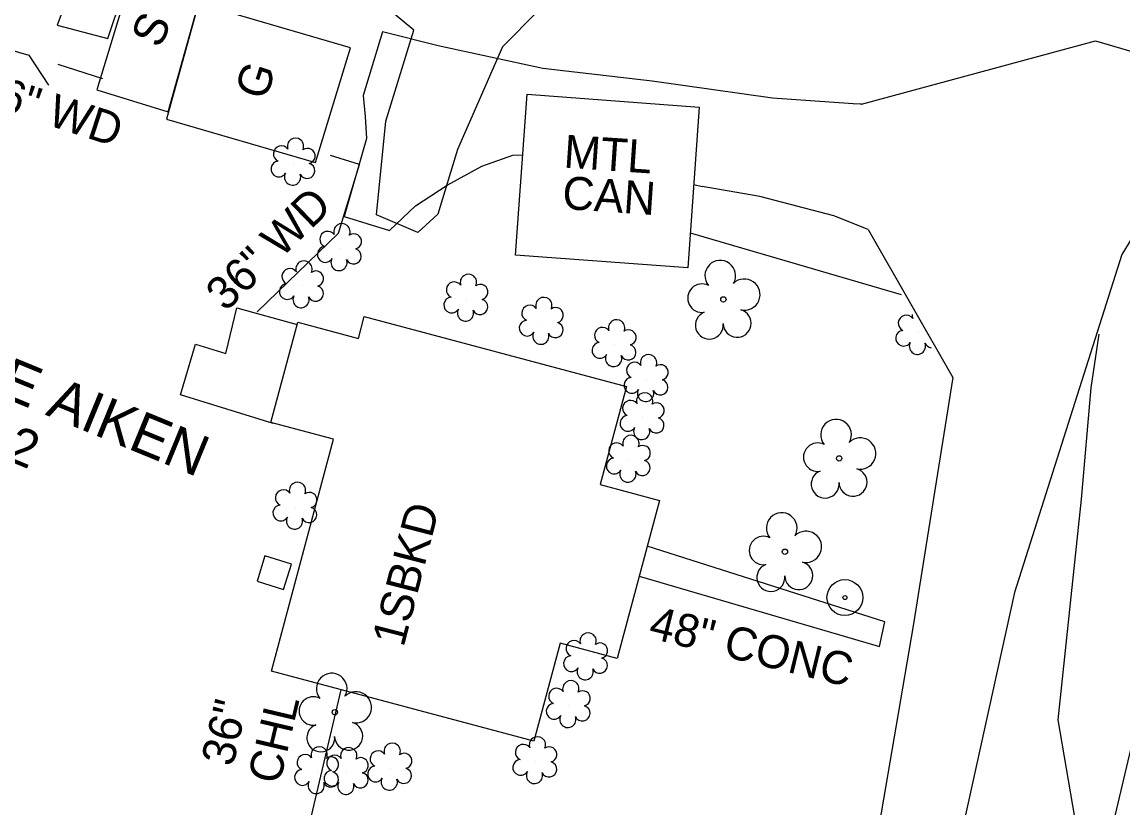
# Model space of a CAD drawing. Extents: x 2089016 to 2094354, y 862840 to 864725.
# Drawn here: x 2091346.4 to 2091480, y 864122.7 to 864218.1 of the extents above; entities that cross this region are included whole.
import ezdxf

# ---------------------------------------------------------------- set-up
doc = ezdxf.new("R2010")
doc.units = 0
for name, color, linetype in [('Exist Building', 7, 'Continuous'), ('Exist Building Metal Canopy', 7, 'Continuous'), ('Exist Building Metal Canopy Text', 7, 'Continuous'), ('Exist Building Text', 7, 'Continuous'), ('Exist Other Culture Area Outline', 7, 'Continuous'), ('Exist Other Culture Area Outline Text', 7, 'Continuous'), ('Exist Other Culture Fence Line', 7, 'Continuous'), ('Exist Other Culture Fence Line Text', 7, 'Continuous'), ('Exist Other Culture Gate', 7, 'Continuous'), ('Exist Property Deed Book Text', 7, 'Continuous'), ('Exist Property Owner Text', 7, 'Continuous'), ('Exist Right of Way Line', 7, 'Continuous'), ('Exist Roads EOP', 7, 'Continuous'), ('Exist Roads Soil', 7, 'Continuous'), ('Exist Vegetation Shrub CELL', 7, 'Continuous'), ('Exist Vegetation Tree CELL', 7, 'Continuous'), ('Exist Vegetation Woods Line', 7, 'Continuous'), ('Prop Drainage Structure Pipe RCP 36in Class IV', 7, 'Continuous')]:
    doc.layers.add(name, color=color, linetype=linetype)

msp = doc.modelspace()

# ---------------------------------------------------------------- linework, layer by layer
at = {"layer": 'Exist Building'}
for points in [[(2091361.02, 864228.09), (2091355.49, 864209.85), (2091364.16, 864207.19), (2091369.4, 864226)], [(2091352.8, 864223.34), (2091350.7, 864217.69), (2091356.82, 864216.07), (2091358.59, 864221.42)], [(2091367.85, 864220.35), (2091363.93, 864206.31), (2091382.04, 864201.05), (2091386.29, 864214.97)], [(2091376.68, 864139.32), (2091384.22, 864167.45), (2091376.6, 864169.49), (2091379.87, 864181.67), (2091387.24, 864179.69), (2091387.95, 864182.36), (2091419.75, 864173.86), (2091416.57, 864161.97), (2091423.77, 864160.04), (2091418.64, 864140.85), (2091411.7, 864142.7), (2091408.52, 864130.81)]]:
    msp.add_lwpolyline(points, close=True, dxfattribs=at)
at = {"layer": 'Exist Building Metal Canopy'}
msp.add_lwpolyline([(2091427.19, 864188.24), (2091406.31, 864189.81), (2091407.71, 864209.34), (2091428.59, 864207.77)], close=True, dxfattribs=at)
at = {"layer": 'Exist Other Culture Area Outline'}
for points in [[(2091376.9, 864169.39), (2091365.66, 864172.84), (2091367.47, 864178.98), (2091371.13, 864177.85), (2091372.47, 864183.4), (2091379.79, 864181.37)], [(2091421.31, 864150.84), (2091450.46, 864142.33), (2091451.11, 864145.32), (2091422.28, 864154.47)]]:
    msp.add_lwpolyline(points, dxfattribs=at)
msp.add_lwpolyline([(2091375.88, 864153.31), (2091374.93, 864150.22), (2091378.16, 864149.23), (2091379.11, 864152.31)], close=True, dxfattribs=at)
at = {"layer": 'Exist Other Culture Fence Line'}
for p, q in [((2091350.75, 864212.96), (2091356.17, 864211.24)), ((2091384.8, 864192.45), (2091374.95, 864182.92)), ((2091427.5, 864192.52), (2091453.07, 864185.04)), ((2091374.68, 864092.67), (2091385.15, 864137.06))]:
    msp.add_line(p, q, dxfattribs=at)
for points in [[(2091361.35, 864227.74), (2091341.2, 864232.73), (2091337.45, 864216.91), (2091347.25, 864214.07)], [(2091384.8, 864192.45), (2091387.35, 864200.79), (2091383.84, 864201.88)]]:
    msp.add_lwpolyline(points, dxfattribs=at)
at = {"layer": 'Exist Other Culture Gate'}
msp.add_line((2091347.25, 864214.07), (2091349.63, 864210.42), dxfattribs=at)
at = {"layer": 'Exist Right of Way Line'}
msp.add_line((2091452.8, 864010.25), (2091484.62, 864145.5), dxfattribs=at)
at = {"layer": 'Exist Roads EOP'}
for points in [[(2091441.1, 863921.91), (2091444.26, 863930.54), (2091451.5, 863951.02), (2091462.11, 863990.03), (2091470.34, 864025.4), (2091478.72, 864061.83), (2091488.18, 864099.79), (2091497.28, 864140.14), (2091508.39, 864182.61), (2091520.43, 864222.63), (2091532.13, 864263.12), (2091539.24, 864279.17)], [(2091458.4, 863915.67), (2091461.42, 863924.49), (2091469.42, 863944.94), (2091479.75, 863985.59), (2091486.04, 864011.02), (2091487.65, 864016.26), (2091489.53, 864018.43), (2091490.64, 864021.54), (2091491.12, 864028.71), (2091491.12, 864035.24), (2091495.79, 864056.26), (2091504.17, 864091.54), (2091506.21, 864096.08), (2091508.03, 864097.81), (2091509.43, 864104.3), (2091510.9, 864108.46), (2091509.69, 864112.64), (2091510.21, 864116.03), (2091515.22, 864135.56), (2091526.19, 864178.07), (2091537.83, 864216.97), (2091551.26, 864256.55)], [(2090159.86, 864177.45), (2090180.67, 864168.73), (2090222.86, 864151.65), (2090264.39, 864134.6), (2090306, 864117.79), (2090347.24, 864101.05), (2090392.99, 864082.57), (2090433.2, 864065.09), (2090472.83, 864048.96), (2090514.73, 864032.43), (2090559.97, 864014.05), (2090601.37, 863997.19), (2090646.29, 863978.82), (2090688.95, 863961.27), (2090733.38, 863942.96), (2090770.05, 863927.33), (2090814.52, 863908.72), (2090858.91, 863891), (2090901.15, 863874.17), (2090939.87, 863858.28), (2090962.72, 863848.64), (2090997.54, 863834.72), (2091036.07, 863819.08), (2091075.6, 863802.48), (2091112.88, 863787.77), (2091153.64, 863770.65), (2091194.67, 863753.49), (2091234.07, 863737.23), (2091276.57, 863719.33), (2091296.56, 863710.75), (2091332.88, 863695.67), (2091370.71, 863680.05), (2091411.45, 863662.85), (2091427.01, 863655.9), (2091440.19, 863646.8), (2091448.83, 863640.62), (2091463.67, 863633.85), (2091467.99, 863632.17), (2091469.11, 863631.07), (2091469.97, 863630.04), (2091470.37, 863629.28)]]:
    msp.add_spline(points, degree=3, dxfattribs=at)
at = {"layer": 'Exist Roads Soil'}
for points in [[(2091447.27, 864208.15), (2091437.46, 864208.85), (2091422.86, 864210.91), (2091409.61, 864212.45), (2091396.9, 864215.21), (2091390.17, 864216.91), (2091387.79, 864209.16), (2091388.04, 864206.63), (2091388.22, 864203.94), (2091385.49, 864194.47), (2091391.01, 864192.77), (2091394.17, 864195.8), (2091398, 864198.28), (2091402.21, 864200.58), (2091405.96, 864201.91), (2091407.18, 864201.96)], [(2091448.26, 864208.12), (2091476.66, 864215.82), (2091492.78, 864211.08)], [(2091448.26, 864208.12), (2091448.09, 864208.12), (2091447.27, 864208.15)], [(2091485.82, 864199.68), (2091479.84, 864189.88), (2091466.83, 864148.87), (2091457.53, 864106.62), (2091449.87, 864069.96), (2091439.63, 864016.58), (2091434.62, 863984.99), (2091437.65, 863966.23)], [(2091427.92, 864198.39), (2091428.95, 864198.14)], [(2091449.09, 864192.9), (2091444.92, 864194.55), (2091435.93, 864196.9), (2091428.95, 864198.14)], [(2091449.09, 864192.9), (2091459.37, 864174.96)], [(2091459.37, 864174.96), (2091454.53, 864144.81), (2091448.34, 864108.66), (2091440.65, 864073.02), (2091430.46, 864019.64), (2091423.86, 863987.54), (2091421.76, 863972.64), (2091359.98, 863988.6), (2091336.21, 863998.07), (2091321.49, 863999.9), (2091315.08, 863979.88), (2091350.22, 863971), (2091390.3, 863962.86), (2091406.39, 863961.4), (2091417.61, 863959.47), (2091429.14, 863943.23)]]:
    msp.add_lwpolyline(points, dxfattribs=at)
at = {"layer": 'Exist Vegetation Shrub CELL'}
for p, q in [((2091379.38, 864200.97), (2091379.38, 864200.97)), ((2091385, 864190.59), (2091385, 864190.59)), ((2091380.4, 864186.08), (2091380.4, 864186.08)), ((2091400.35, 864184.46), (2091400.35, 864184.46)), ((2091409.5, 864181.65), (2091409.5, 864181.65)), ((2091455.18, 864180.43), (2091455.18, 864180.43)), ((2091418.33, 864178.94), (2091418.33, 864178.94)), ((2091422.21, 864174.71), (2091422.21, 864174.71)), ((2091421.73, 864170.08), (2091421.73, 864170.08)), ((2091420.06, 864164.91), (2091420.06, 864164.91)), ((2091379.61, 864159.22), (2091379.61, 864159.22)), ((2091414.87, 864140.94), (2091414.87, 864140.94)), ((2091412.77, 864135.14), (2091412.77, 864135.14)), ((2091408.72, 864128.34), (2091408.72, 864128.34)), ((2091382.24, 864127.12), (2091382.24, 864127.12)), ((2091385.83, 864127.03), (2091385.83, 864127.03)), ((2091391.11, 864127.56), (2091391.11, 864127.56))]:
    msp.add_line(p, q, dxfattribs=at)
for centre, radius, start, end in [((2091379.6, 864203.01), 0.99, 334.8391, 200.4717), ((2091377.89, 864202.09), 0.968, 35.8908, 245.4216), ((2091381.05, 864201.83), 0.929, 284.4567, 126.0861), ((2091377.58, 864200.26), 0.955, 95.1099, 327.9534), ((2091381.01, 864200.04), 0.937, 204.9913, 73.4601), ((2091379.25, 864199.28), 0.984, 151.2797, 21.387), ((2091383.52, 864191.72), 0.968, 35.8908, 245.4216), ((2091385.23, 864192.63), 0.99, 334.8391, 200.4717), ((2091386.68, 864191.46), 0.929, 284.4567, 126.0861), ((2091383.2, 864189.88), 0.955, 95.1099, 327.9534), ((2091386.64, 864189.66), 0.937, 204.9913, 73.4601), ((2091380.63, 864188.12), 0.99, 334.8391, 200.4717), ((2091384.88, 864188.9), 0.984, 151.2797, 21.387), ((2091378.92, 864187.21), 0.968, 35.8908, 245.4216), ((2091382.07, 864186.95), 0.929, 284.4567, 126.0861), ((2091400.58, 864186.5), 0.99, 334.8391, 200.4717), ((2091378.6, 864185.38), 0.955, 95.1099, 327.9534), ((2091382.04, 864185.15), 0.937, 204.9913, 73.4601), ((2091398.87, 864185.58), 0.968, 35.8908, 245.4216), ((2091402.02, 864185.32), 0.929, 284.4567, 126.0861), ((2091380.27, 864184.4), 0.984, 151.2797, 21.387), ((2091398.55, 864183.75), 0.955, 95.1099, 327.9534), ((2091401.99, 864183.53), 0.937, 204.9913, 73.4601), ((2091409.73, 864183.69), 0.99, 334.8391, 200.4717), ((2091400.22, 864182.77), 0.984, 151.2797, 21.387), ((2091408.02, 864182.77), 0.968, 35.8908, 245.4216), ((2091411.17, 864182.51), 0.929, 284.4567, 126.0861), ((2091407.7, 864180.94), 0.955, 95.1099, 327.9534), ((2091418.56, 864180.98), 0.99, 334.8391, 200.4717), ((2091453.7, 864181.55), 0.968, 35.8908, 245.4216), ((2091455.41, 864182.47), 0.99, 171.5683, 200.4717), ((2091409.37, 864179.96), 0.984, 151.2797, 21.387), ((2091411.14, 864180.72), 0.937, 204.9913, 73.4601), ((2091416.85, 864180.07), 0.968, 35.8908, 245.4216), ((2091420, 864179.81), 0.929, 284.4567, 126.0861), ((2091453.38, 864179.72), 0.955, 95.1099, 327.9534), ((2091416.53, 864178.24), 0.955, 95.1099, 327.9534), ((2091455.05, 864178.74), 0.984, 151.2797, 21.387), ((2091456.82, 864179.5), 0.937, 204.9913, 262.7605), ((2091418.2, 864177.26), 0.984, 151.2797, 21.387), ((2091419.97, 864178.01), 0.937, 204.9913, 73.4601), ((2091422.44, 864176.75), 0.99, 334.8391, 200.4717), ((2091420.73, 864175.84), 0.968, 35.8908, 245.4216), ((2091423.88, 864175.58), 0.929, 284.4567, 126.0861), ((2091420.41, 864174.01), 0.955, 95.1099, 327.9534), ((2091423.85, 864173.78), 0.937, 204.9913, 73.4601), ((2091421.96, 864172.12), 0.99, 334.8391, 200.4717), ((2091422.08, 864173.03), 0.984, 151.2797, 21.387), ((2091420.25, 864171.21), 0.968, 35.8908, 245.4216), ((2091423.4, 864170.95), 0.929, 284.4567, 126.0861), ((2091419.93, 864169.38), 0.955, 95.1099, 327.9534), ((2091423.37, 864169.15), 0.937, 204.9913, 73.4601), ((2091421.6, 864168.4), 0.984, 151.2797, 21.387), ((2091420.29, 864166.95), 0.99, 334.8391, 200.4717), ((2091418.57, 864166.04), 0.968, 35.8908, 245.4216), ((2091421.73, 864165.78), 0.929, 284.4567, 126.0861), ((2091418.26, 864164.21), 0.955, 95.1099, 327.9534), ((2091421.69, 864163.98), 0.937, 204.9913, 73.4601), ((2091419.93, 864163.23), 0.984, 151.2797, 21.387), ((2091379.84, 864161.26), 0.99, 334.8391, 200.4717), ((2091378.13, 864160.35), 0.968, 35.8908, 245.4216), ((2091381.28, 864160.09), 0.929, 284.4567, 126.0861), ((2091377.81, 864158.52), 0.955, 95.1099, 327.9534), ((2091381.25, 864158.29), 0.937, 204.9913, 73.4601), ((2091379.48, 864157.54), 0.984, 151.2797, 21.387), ((2091413.39, 864142.07), 0.968, 35.8908, 245.4216), ((2091415.1, 864142.98), 0.99, 334.8391, 200.4717), ((2091416.54, 864141.81), 0.929, 284.4567, 126.0861), ((2091413.07, 864140.23), 0.955, 95.1099, 327.9534), ((2091416.51, 864140.01), 0.937, 204.9913, 73.4601), ((2091414.74, 864139.26), 0.984, 151.2797, 21.387), ((2091413, 864137.18), 0.99, 334.8391, 200.4717), ((2091411.29, 864136.27), 0.968, 35.8908, 245.4216), ((2091414.44, 864136.01), 0.929, 284.4567, 126.0861), ((2091410.97, 864134.44), 0.955, 95.1099, 327.9534), ((2091414.41, 864134.21), 0.937, 204.9913, 73.4601), ((2091412.64, 864133.46), 0.984, 151.2797, 21.387), ((2091408.95, 864130.38), 0.99, 334.8391, 200.4717), ((2091382.47, 864129.16), 0.99, 334.8391, 200.4717), ((2091386.06, 864129.07), 0.99, 334.8391, 200.4717), ((2091389.62, 864128.68), 0.968, 35.8908, 245.4216), ((2091391.33, 864129.6), 0.99, 334.8391, 200.4717), ((2091407.24, 864129.47), 0.968, 35.8908, 245.4216), ((2091410.39, 864129.21), 0.929, 284.4567, 126.0861), ((2091380.76, 864128.25), 0.968, 35.8908, 245.4216), ((2091383.91, 864127.99), 0.929, 284.4567, 126.0861), ((2091384.35, 864128.16), 0.968, 35.8908, 245.4216), ((2091387.51, 864127.9), 0.929, 284.4567, 126.0861), ((2091392.78, 864128.43), 0.929, 284.4567, 126.0861), ((2091406.92, 864127.64), 0.955, 95.1099, 327.9534), ((2091410.36, 864127.41), 0.937, 204.9913, 73.4601), ((2091380.44, 864126.42), 0.955, 95.1099, 327.9534), ((2091383.88, 864126.19), 0.937, 204.9913, 73.4601), ((2091384.03, 864126.33), 0.955, 95.1099, 327.9534), ((2091387.47, 864126.1), 0.937, 204.9913, 73.4601), ((2091389.31, 864126.85), 0.955, 95.1099, 327.9534), ((2091392.74, 864126.63), 0.937, 204.9913, 73.4601), ((2091408.59, 864126.66), 0.984, 151.2797, 21.387), ((2091382.11, 864125.44), 0.984, 151.2797, 21.387), ((2091385.71, 864125.35), 0.984, 151.2797, 21.387), ((2091390.98, 864125.87), 0.984, 151.2797, 21.387)]:
    msp.add_arc(centre, radius, start, end, dxfattribs=at)
at = {"layer": 'Exist Vegetation Tree CELL'}
for p, q in [((2091431.51, 864184.43), (2091431.51, 864184.43)), ((2091445.56, 864165.14), (2091445.56, 864165.14)), ((2091438.98, 864153.81), (2091438.98, 864153.81)), ((2091384.37, 864134.34), (2091384.37, 864134.34))]:
    msp.add_line(p, q, dxfattribs=at)
for centre in [(2091431.51, 864184.43), (2091445.56, 864165.14), (2091438.98, 864153.81), (2091384.37, 864134.34)]:
    msp.add_circle(centre, 0.326, dxfattribs=at)
for centre, radius, start, end in [((2091431.13, 864187.3), 1.86, 330.1651, 219.7134), ((2091428.91, 864184.58), 1.73, 62.6636, 279.3457), ((2091434.06, 864185.01), 1.9, 257.1011, 134.1999), ((2091433.18, 864181.53), 1.7, 181.2822, 74.56), ((2091429.81, 864181.3), 1.69, 111.5671, 6.231), ((2091445.18, 864168.01), 1.86, 330.1651, 219.7134), ((2091448.11, 864165.73), 1.9, 257.1011, 134.1999), ((2091442.96, 864165.29), 1.73, 62.6636, 279.3457), ((2091443.86, 864162.02), 1.69, 111.5671, 6.231), ((2091447.24, 864162.24), 1.7, 181.2822, 74.56), ((2091438.59, 864156.68), 1.86, 330.1651, 219.7134), ((2091436.37, 864153.96), 1.73, 62.6636, 279.3457), ((2091441.53, 864154.4), 1.9, 257.1011, 134.1999), ((2091440.65, 864150.91), 1.7, 181.2822, 74.56), ((2091437.27, 864150.69), 1.69, 111.5671, 6.231), ((2091383.99, 864137.21), 1.86, 330.1651, 219.7134), ((2091386.92, 864134.93), 1.9, 257.1011, 134.1999), ((2091381.77, 864134.49), 1.73, 62.6636, 279.3457), ((2091382.67, 864131.22), 1.69, 111.5671, 6.231), ((2091386.05, 864131.44), 1.7, 181.2822, 74.56)]:
    msp.add_arc(centre, radius, start, end, dxfattribs=at)
at = {"layer": 'Exist Vegetation Woods Line'}
for points in [[(2091413.37, 864223.87), (2091404.73, 864215.09), (2091399.27, 864202.63), (2091396.85, 864194.77), (2091394.43, 864192.54), (2091389.41, 864194.7), (2091390.55, 864206.04), (2091393.94, 864217.09), (2091386.41, 864223.4)], [(2091504.86, 864199.82), (2091496.91, 864185.12), (2091491.46, 864169.89), (2091486.99, 864147.5), (2091483.15, 864125.89), (2091481.19, 864119.69), (2091474.16, 864121.62), (2091472.11, 864133.4), (2091474.95, 864160.18), (2091476.13, 864173.68), (2091477.1, 864180.2)]]:
    msp.add_lwpolyline(points, dxfattribs=at)
at = {"layer": 'Prop Drainage Structure Pipe RCP 36in Class IV'}
for radius in [2.18, 0.24]:
    msp.add_circle((2091446.26, 864148.25), radius, dxfattribs=at)

# ---------------------------------------------------------------- texts
at = {"layer": 'Exist Building Metal Canopy Text'}
for s, p in [('MTL', (2091412.06, 864200.43)), ('CAN', (2091411.88, 864195.42))]:
    msp.add_text(s, height=4, rotation=356.1194, dxfattribs=at).set_placement(p)
at = {"layer": 'Exist Building Text'}
for s, rotation, p in [('S', 66.0057, (2091363.16, 864214.77)), ('G', 71.9365, (2091375.98, 864208.46)), ('36" WD', 342.0219, (2091340.44, 864208.52)), ('1SBKD', 75.5633, (2091392.71, 864142.12))]:
    msp.add_text(s, height=4, rotation=rotation, dxfattribs=at).set_placement(p)
at = {"layer": 'Exist Other Culture Area Outline Text'}
msp.add_text('48" CONC', height=4, rotation=346.1643, dxfattribs=at).set_placement((2091422.28, 864143.39))
at = {"layer": 'Exist Other Culture Fence Line Text'}
for s, rotation, p in [('36" WD', 44.08, (2091371.12, 864182.84)), ('36" ', 76.7313, (2091372, 864127.63)), ('CHL', 76.7313, (2091377.65, 864125.45))]:
    msp.add_text(s, height=4, rotation=rotation, dxfattribs=at).set_placement(p)
at = {"layer": 'Exist Property Deed Book Text'}
msp.add_text('DB 1160 PG 312', height=4.5, rotation=337.6724, dxfattribs=at).set_placement((2091305.22, 864181.08))
at = {"layer": 'Exist Property Owner Text'}
msp.add_text('LYNN & ALICE AIKEN', height=5, rotation=337.6724, dxfattribs=at).set_placement((2091305.49, 864188.39))

doc.saveas('drawing.dxf')
